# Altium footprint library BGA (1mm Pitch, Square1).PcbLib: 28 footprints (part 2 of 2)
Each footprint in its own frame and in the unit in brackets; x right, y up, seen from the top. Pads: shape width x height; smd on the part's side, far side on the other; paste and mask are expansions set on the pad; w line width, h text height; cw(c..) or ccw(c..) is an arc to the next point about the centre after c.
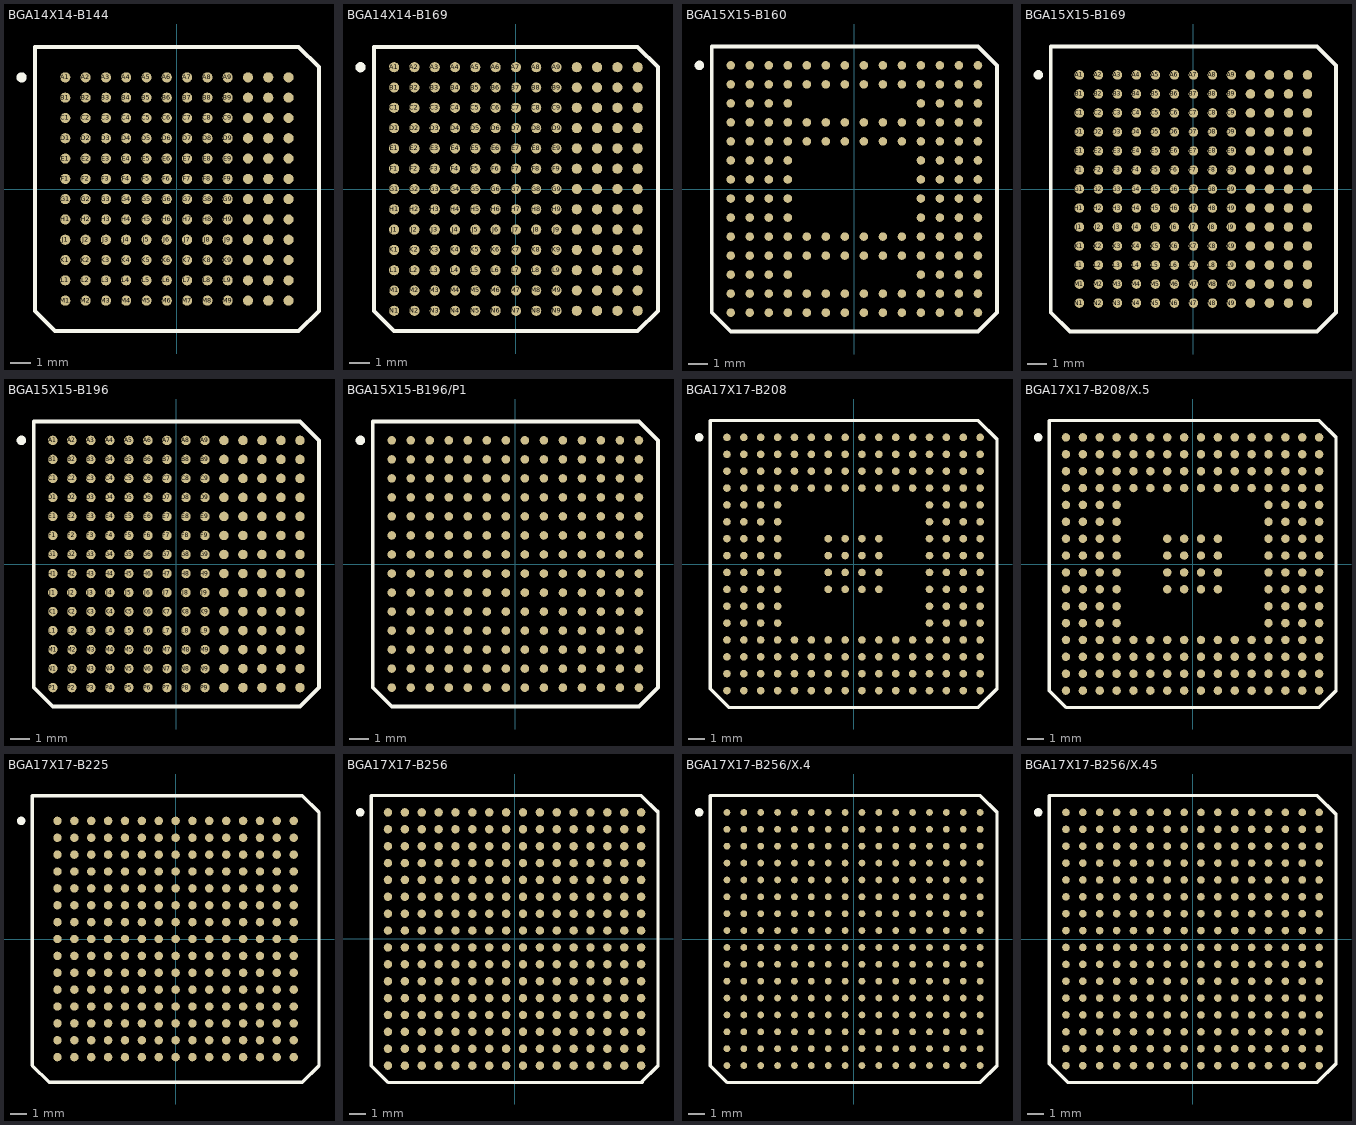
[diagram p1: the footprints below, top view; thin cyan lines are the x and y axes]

## BGA14X14-B144 [mm]
pads (144):
  round 0.5 smd: A1(-5.5,5.5) A2(-4.5,5.5) A3(-3.5,5.5) A4(-2.5,5.5) A5(-1.5,5.5) A6(-0.5,5.5) A7(0.5,5.5) A8(1.5,5.5) A9(2.5,5.5) A10(3.5,5.5) A11(4.5,5.5) A12(5.5,5.5) B1(-5.5,4.5) B2(-4.5,4.5) B3(-3.5,4.5) B4(-2.5,4.5) B5(-1.5,4.5) B6(-0.5,4.5) B7(0.5,4.5) B8(1.5,4.5) B9(2.5,4.5) B10(3.5,4.5) B11(4.5,4.5) B12(5.5,4.5) C1(-5.5,3.5) C2(-4.5,3.5) C3(-3.5,3.5) C4(-2.5,3.5) C5(-1.5,3.5) C6(-0.5,3.5) C7(0.5,3.5) C8(1.5,3.5) C9(2.5,3.5) C10(3.5,3.5) C11(4.5,3.5) C12(5.5,3.5) D1(-5.5,2.5) D2(-4.5,2.5) D3(-3.5,2.5) D4(-2.5,2.5) D5(-1.5,2.5) D6(-0.5,2.5) D7(0.5,2.5) D8(1.5,2.5) D9(2.5,2.5) D10(3.5,2.5) D11(4.5,2.5) D12(5.5,2.5) E1(-5.5,1.5) E2(-4.5,1.5) E3(-3.5,1.5) E4(-2.5,1.5) E5(-1.5,1.5) E6(-0.5,1.5) E7(0.5,1.5) E8(1.5,1.5) E9(2.5,1.5) E10(3.5,1.5) E11(4.5,1.5) E12(5.5,1.5) F1(-5.5,0.5) F2(-4.5,0.5) F3(-3.5,0.5) F4(-2.5,0.5) F5(-1.5,0.5) F6(-0.5,0.5) F7(0.5,0.5) F8(1.5,0.5) F9(2.5,0.5) F10(3.5,0.5) F11(4.5,0.5) F12(5.5,0.5) G1(-5.5,-0.5) G2(-4.5,-0.5) G3(-3.5,-0.5) G4(-2.5,-0.5) G5(-1.5,-0.5) G6(-0.5,-0.5) G7(0.5,-0.5) G8(1.5,-0.5) G9(2.5,-0.5) G10(3.5,-0.5) G11(4.5,-0.5) G12(5.5,-0.5) H1(-5.5,-1.5) H2(-4.5,-1.5) H3(-3.5,-1.5) H4(-2.5,-1.5) H5(-1.5,-1.5) H6(-0.5,-1.5) H7(0.5,-1.5) H8(1.5,-1.5) H9(2.5,-1.5) H10(3.5,-1.5) H11(4.5,-1.5) H12(5.5,-1.5) J1(-5.5,-2.5) J2(-4.5,-2.5) J3(-3.5,-2.5) J4(-2.5,-2.5) J5(-1.5,-2.5) J6(-0.5,-2.5) J7(0.5,-2.5) J8(1.5,-2.5) J9(2.5,-2.5) J10(3.5,-2.5) J11(4.5,-2.5) J12(5.5,-2.5) K1(-5.5,-3.5) K2(-4.5,-3.5) K3(-3.5,-3.5) K4(-2.5,-3.5) K5(-1.5,-3.5) K6(-0.5,-3.5) K7(0.5,-3.5) K8(1.5,-3.5) K9(2.5,-3.5) K10(3.5,-3.5) K11(4.5,-3.5) K12(5.5,-3.5) L1(-5.5,-4.5) L2(-4.5,-4.5) L3(-3.5,-4.5) L4(-2.5,-4.5) L5(-1.5,-4.5) L6(-0.5,-4.5) L7(0.5,-4.5) L8(1.5,-4.5) L9(2.5,-4.5) L10(3.5,-4.5) L11(4.5,-4.5) L12(5.5,-4.5) M1(-5.5,-5.5) M2(-4.5,-5.5) M3(-3.5,-5.5) M4(-2.5,-5.5) M5(-1.5,-5.5) M6(-0.5,-5.5) M7(0.5,-5.5) M8(1.5,-5.5) M9(2.5,-5.5) M10(3.5,-5.5) M11(4.5,-5.5) M12(5.5,-5.5)
Top Overlay:
  circle w0.25: c-7.655,5.5 r0.125
  lines w0.2: -7,-6 -6,-7 6,-7 7,-6 7,6 6,7 -7,7 -7,-6

## BGA14X14-B169 [mm]
pads (169):
  round 0.5 smd: A1(-6,6) A2(-5,6) A3(-4,6) A4(-3,6) A5(-2,6) A6(-1,6) A7(0,6) A8(1,6) A9(2,6) A10(3,6) A11(4,6) A12(5,6) A13(6,6) B1(-6,5) B2(-5,5) B3(-4,5) B4(-3,5) B5(-2,5) B6(-1,5) B7(0,5) B8(1,5) B9(2,5) B10(3,5) B11(4,5) B12(5,5) B13(6,5) C1(-6,4) C2(-5,4) C3(-4,4) C4(-3,4) C5(-2,4) C6(-1,4) C7(0,4) C8(1,4) C9(2,4) C10(3,4) C11(4,4) C12(5,4) C13(6,4) D1(-6,3) D2(-5,3) D3(-4,3) D4(-3,3) D5(-2,3) D6(-1,3) D7(0,3) D8(1,3) D9(2,3) D10(3,3) D11(4,3) D12(5,3) D13(6,3) E1(-6,2) E2(-5,2) E3(-4,2) E4(-3,2) E5(-2,2) E6(-1,2) E7(0,2) E8(1,2) E9(2,2) E10(3,2) E11(4,2) E12(5,2) E13(6,2) F1(-6,1) F2(-5,1) F3(-4,1) F4(-3,1) F5(-2,1) F6(-1,1) F7(0,1) F8(1,1) F9(2,1) F10(3,1) F11(4,1) F12(5,1) F13(6,1) G1(-6,0) G2(-5,0) G3(-4,0) G4(-3,0) G5(-2,0) G6(-1,0) G7(0,0) G8(1,0) G9(2,0) G10(3,0) G11(4,0) G12(5,0) G13(6,0) H1(-6,-1) H2(-5,-1) H3(-4,-1) H4(-3,-1) H5(-2,-1) H6(-1,-1) H7(0,-1) H8(1,-1) H9(2,-1) H10(3,-1) H11(4,-1) H12(5,-1) H13(6,-1) J1(-6,-2) J2(-5,-2) J3(-4,-2) J4(-3,-2) J5(-2,-2) J6(-1,-2) J7(0,-2) J8(1,-2) J9(2,-2) J10(3,-2) J11(4,-2) J12(5,-2) J13(6,-2) K1(-6,-3) K2(-5,-3) K3(-4,-3) K4(-3,-3) K5(-2,-3) K6(-1,-3) K7(0,-3) K8(1,-3) K9(2,-3) K10(3,-3) K11(4,-3) K12(5,-3) K13(6,-3) L1(-6,-4) L2(-5,-4) L3(-4,-4) L4(-3,-4) L5(-2,-4) L6(-1,-4) L7(0,-4) L8(1,-4) L9(2,-4) L10(3,-4) L11(4,-4) L12(5,-4) L13(6,-4) M1(-6,-5) M2(-5,-5) M3(-4,-5) M4(-3,-5) M5(-2,-5) M6(-1,-5) M7(0,-5) M8(1,-5) M9(2,-5) M10(3,-5) M11(4,-5) M12(5,-5) M13(6,-5) N1(-6,-6) N2(-5,-6) N3(-4,-6) N4(-3,-6) N5(-2,-6) N6(-1,-6) N7(0,-6) N8(1,-6) N9(2,-6) N10(3,-6) N11(4,-6) N12(5,-6) N13(6,-6)
Top Overlay:
  circle w0.25: c-7.655,6 r0.125
  lines w0.2: -7,-6 -7,7 6,7 7,6 7,-6 6,-7 -6,-7 -7,-6

## BGA15X15-B160 [mm]
pads (160):
  round 0.45 smd: A1(-6.5,6.5) A2(-5.5,6.5) A3(-4.5,6.5) A4(-3.5,6.5) A5(-2.5,6.5) A6(-1.5,6.5) A7(-0.5,6.5) A8(0.5,6.5) A9(1.5,6.5) A10(2.5,6.5) A11(3.5,6.5) A12(4.5,6.5) A13(5.5,6.5) A14(6.5,6.5) B1(-6.5,5.5) B2(-5.5,5.5) B3(-4.5,5.5) B4(-3.5,5.5) B5(-2.5,5.5) B6(-1.5,5.5) B7(-0.5,5.5) B8(0.5,5.5) B9(1.5,5.5) B10(2.5,5.5) B11(3.5,5.5) B12(4.5,5.5) B13(5.5,5.5) B14(6.5,5.5) C1(-6.5,4.5) C2(-5.5,4.5) C3(-4.5,4.5) C4(-3.5,4.5) C11(3.5,4.5) C12(4.5,4.5) C13(5.5,4.5) C14(6.5,4.5) D1(-6.5,3.5) D2(-5.5,3.5) D3(-4.5,3.5) D4(-3.5,3.5) D5(-2.5,3.5) D6(-1.5,3.5) D7(-0.5,3.5) D8(0.5,3.5) D9(1.5,3.5) D10(2.5,3.5) D11(3.5,3.5) D12(4.5,3.5) D13(5.5,3.5) D14(6.5,3.5) E1(-6.5,2.5) E2(-5.5,2.5) E3(-4.5,2.5) E4(-3.5,2.5) E5(-2.5,2.5) E6(-1.5,2.5) E7(-0.5,2.5) E8(0.5,2.5) E9(1.5,2.5) E10(2.5,2.5) E11(3.5,2.5) E12(4.5,2.5) E13(5.5,2.5) E14(6.5,2.5) F1(-6.5,1.5) F2(-5.5,1.5) F3(-4.5,1.5) F4(-3.5,1.5) F11(3.5,1.5) F12(4.5,1.5) F13(5.5,1.5) F14(6.5,1.5) G1(-6.5,0.5) G2(-5.5,0.5) G3(-4.5,0.5) G4(-3.5,0.5) G11(3.5,0.5) G12(4.5,0.5) G13(5.5,0.5) G14(6.5,0.5) H1(-6.5,-0.5) H2(-5.5,-0.5) H3(-4.5,-0.5) H4(-3.5,-0.5) H11(3.5,-0.5) H12(4.5,-0.5) H13(5.5,-0.5) H14(6.5,-0.5) J1(-6.5,-1.5) J2(-5.5,-1.5) J3(-4.5,-1.5) J4(-3.5,-1.5) J11(3.5,-1.5) J12(4.5,-1.5) J13(5.5,-1.5) J14(6.5,-1.5) K1(-6.5,-2.5) K2(-5.5,-2.5) K3(-4.5,-2.5) K4(-3.5,-2.5) K5(-2.5,-2.5) K6(-1.5,-2.5) K7(-0.5,-2.5) K8(0.5,-2.5) K9(1.5,-2.5) K10(2.5,-2.5) K11(3.5,-2.5) K12(4.5,-2.5) K13(5.5,-2.5) K14(6.5,-2.5) L1(-6.5,-3.5) L2(-5.5,-3.5) L3(-4.5,-3.5) L4(-3.5,-3.5) L5(-2.5,-3.5) L6(-1.5,-3.5) L7(-0.5,-3.5) L8(0.5,-3.5) L9(1.5,-3.5) L10(2.5,-3.5) L11(3.5,-3.5) L12(4.5,-3.5) L13(5.5,-3.5) L14(6.5,-3.5) M1(-6.5,-4.5) M2(-5.5,-4.5) M3(-4.5,-4.5) M4(-3.5,-4.5) M11(3.5,-4.5) M12(4.5,-4.5) M13(5.5,-4.5) M14(6.5,-4.5) N1(-6.5,-5.5) N2(-5.5,-5.5) N3(-4.5,-5.5) N4(-3.5,-5.5) N5(-2.5,-5.5) N6(-1.5,-5.5) N7(-0.5,-5.5) N8(0.5,-5.5) N9(1.5,-5.5) N10(2.5,-5.5) N11(3.5,-5.5) N12(4.5,-5.5) N13(5.5,-5.5) N14(6.5,-5.5) P1(-6.5,-6.5) P2(-5.5,-6.5) P3(-4.5,-6.5) P4(-3.5,-6.5) P5(-2.5,-6.5) P6(-1.5,-6.5) P7(-0.5,-6.5) P8(0.5,-6.5) P9(1.5,-6.5) P10(2.5,-6.5) P11(3.5,-6.5) P12(4.5,-6.5) P13(5.5,-6.5) P14(6.5,-6.5)
Top Overlay:
  circle w0.25: c-8.15,6.5 r0.125
  lines w0.2: -7.5,-6.5 -7.5,7.5 6.5,7.5 7.5,6.5 7.5,-6.5 6.5,-7.5 -6.5,-7.5 -7.5,-6.5

## BGA15X15-B169 [mm]
pads (169):
  round 0.5 smd: A1(-6,6) A2(-5,6) A3(-4,6) A4(-3,6) A5(-2,6) A6(-1,6) A7(0,6) A8(1,6) A9(2,6) A10(3,6) A11(4,6) A12(5,6) A13(6,6) B1(-6,5) B2(-5,5) B3(-4,5) B4(-3,5) B5(-2,5) B6(-1,5) B7(0,5) B8(1,5) B9(2,5) B10(3,5) B11(4,5) B12(5,5) B13(6,5) C1(-6,4) C2(-5,4) C3(-4,4) C4(-3,4) C5(-2,4) C6(-1,4) C7(0,4) C8(1,4) C9(2,4) C10(3,4) C11(4,4) C12(5,4) C13(6,4) D1(-6,3) D2(-5,3) D3(-4,3) D4(-3,3) D5(-2,3) D6(-1,3) D7(0,3) D8(1,3) D9(2,3) D10(3,3) D11(4,3) D12(5,3) D13(6,3) E1(-6,2) E2(-5,2) E3(-4,2) E4(-3,2) E5(-2,2) E6(-1,2) E7(0,2) E8(1,2) E9(2,2) E10(3,2) E11(4,2) E12(5,2) E13(6,2) F1(-6,1) F2(-5,1) F3(-4,1) F4(-3,1) F5(-2,1) F6(-1,1) F7(0,1) F8(1,1) F9(2,1) F10(3,1) F11(4,1) F12(5,1) F13(6,1) G1(-6,0) G2(-5,0) G3(-4,0) G4(-3,0) G5(-2,0) G6(-1,0) G7(0,0) G8(1,0) G9(2,0) G10(3,0) G11(4,0) G12(5,0) G13(6,0) H1(-6,-1) H2(-5,-1) H3(-4,-1) H4(-3,-1) H5(-2,-1) H6(-1,-1) H7(0,-1) H8(1,-1) H9(2,-1) H10(3,-1) H11(4,-1) H12(5,-1) H13(6,-1) J1(-6,-2) J2(-5,-2) J3(-4,-2) J4(-3,-2) J5(-2,-2) J6(-1,-2) J7(0,-2) J8(1,-2) J9(2,-2) J10(3,-2) J11(4,-2) J12(5,-2) J13(6,-2) K1(-6,-3) K2(-5,-3) K3(-4,-3) K4(-3,-3) K5(-2,-3) K6(-1,-3) K7(0,-3) K8(1,-3) K9(2,-3) K10(3,-3) K11(4,-3) K12(5,-3) K13(6,-3) L1(-6,-4) L2(-5,-4) L3(-4,-4) L4(-3,-4) L5(-2,-4) L6(-1,-4) L7(0,-4) L8(1,-4) L9(2,-4) L10(3,-4) L11(4,-4) L12(5,-4) L13(6,-4) M1(-6,-5) M2(-5,-5) M3(-4,-5) M4(-3,-5) M5(-2,-5) M6(-1,-5) M7(0,-5) M8(1,-5) M9(2,-5) M10(3,-5) M11(4,-5) M12(5,-5) M13(6,-5) N1(-6,-6) N2(-5,-6) N3(-4,-6) N4(-3,-6) N5(-2,-6) N6(-1,-6) N7(0,-6) N8(1,-6) N9(2,-6) N10(3,-6) N11(4,-6) N12(5,-6) N13(6,-6)
Top Overlay:
  circle w0.25: c-8.155,6 r0.125
  lines w0.2: -7.5,-6.5 -7.5,7.5 6.5,7.5 7.5,6.5 7.5,-6.5 6.5,-7.5 -6.5,-7.5 -7.5,-6.5

## BGA15X15-B196 [mm]
pads (196):
  round 0.5 smd: A1(-6.5,6.5) A2(-5.5,6.5) A3(-4.5,6.5) A4(-3.5,6.5) A5(-2.5,6.5) A6(-1.5,6.5) A7(-0.5,6.5) A8(0.5,6.5) A9(1.5,6.5) A10(2.5,6.5) A11(3.5,6.5) A12(4.5,6.5) A13(5.5,6.5) A14(6.5,6.5) B1(-6.5,5.5) B2(-5.5,5.5) B3(-4.5,5.5) B4(-3.5,5.5) B5(-2.5,5.5) B6(-1.5,5.5) B7(-0.5,5.5) B8(0.5,5.5) B9(1.5,5.5) B10(2.5,5.5) B11(3.5,5.5) B12(4.5,5.5) B13(5.5,5.5) B14(6.5,5.5) C1(-6.5,4.5) C2(-5.5,4.5) C3(-4.5,4.5) C4(-3.5,4.5) C5(-2.5,4.5) C6(-1.5,4.5) C7(-0.5,4.5) C8(0.5,4.5) C9(1.5,4.5) C10(2.5,4.5) C11(3.5,4.5) C12(4.5,4.5) C13(5.5,4.5) C14(6.5,4.5) D1(-6.5,3.5) D2(-5.5,3.5) D3(-4.5,3.5) D4(-3.5,3.5) D5(-2.5,3.5) D6(-1.5,3.5) D7(-0.5,3.5) D8(0.5,3.5) D9(1.5,3.5) D10(2.5,3.5) D11(3.5,3.5) D12(4.5,3.5) D13(5.5,3.5) D14(6.5,3.5) E1(-6.5,2.5) E2(-5.5,2.5) E3(-4.5,2.5) E4(-3.5,2.5) E5(-2.5,2.5) E6(-1.5,2.5) E7(-0.5,2.5) E8(0.5,2.5) E9(1.5,2.5) E10(2.5,2.5) E11(3.5,2.5) E12(4.5,2.5) E13(5.5,2.5) E14(6.5,2.5) F1(-6.5,1.5) F2(-5.5,1.5) F3(-4.5,1.5) F4(-3.5,1.5) F5(-2.5,1.5) F6(-1.5,1.5) F7(-0.5,1.5) F8(0.5,1.5) F9(1.5,1.5) F10(2.5,1.5) F11(3.5,1.5) F12(4.5,1.5) F13(5.5,1.5) F14(6.5,1.5) G1(-6.5,0.5) G2(-5.5,0.5) G3(-4.5,0.5) G4(-3.5,0.5) G5(-2.5,0.5) G6(-1.5,0.5) G7(-0.5,0.5) G8(0.5,0.5) G9(1.5,0.5) G10(2.5,0.5) G11(3.5,0.5) G12(4.5,0.5) G13(5.5,0.5) G14(6.5,0.5) H1(-6.5,-0.5) H2(-5.5,-0.5) H3(-4.5,-0.5) H4(-3.5,-0.5) H5(-2.5,-0.5) H6(-1.5,-0.5) H7(-0.5,-0.5) H8(0.5,-0.5) H9(1.5,-0.5) H10(2.5,-0.5) H11(3.5,-0.5) H12(4.5,-0.5) H13(5.5,-0.5) H14(6.5,-0.5) J1(-6.5,-1.5) J2(-5.5,-1.5) J3(-4.5,-1.5) J4(-3.5,-1.5) J5(-2.5,-1.5) J6(-1.5,-1.5) J7(-0.5,-1.5) J8(0.5,-1.5) J9(1.5,-1.5) J10(2.5,-1.5) J11(3.5,-1.5) J12(4.5,-1.5) J13(5.5,-1.5) J14(6.5,-1.5) K1(-6.5,-2.5) K2(-5.5,-2.5) K3(-4.5,-2.5) K4(-3.5,-2.5) K5(-2.5,-2.5) K6(-1.5,-2.5) K7(-0.5,-2.5) K8(0.5,-2.5) K9(1.5,-2.5) K10(2.5,-2.5) K11(3.5,-2.5) K12(4.5,-2.5) K13(5.5,-2.5) K14(6.5,-2.5) L1(-6.5,-3.5) L2(-5.5,-3.5) L3(-4.5,-3.5) L4(-3.5,-3.5) L5(-2.5,-3.5) L6(-1.5,-3.5) L7(-0.5,-3.5) L8(0.5,-3.5) L9(1.5,-3.5) L10(2.5,-3.5) L11(3.5,-3.5) L12(4.5,-3.5) L13(5.5,-3.5) L14(6.5,-3.5) M1(-6.5,-4.5) M2(-5.5,-4.5) M3(-4.5,-4.5) M4(-3.5,-4.5) M5(-2.5,-4.5) M6(-1.5,-4.5) M7(-0.5,-4.5) M8(0.5,-4.5) M9(1.5,-4.5) M10(2.5,-4.5) M11(3.5,-4.5) M12(4.5,-4.5) M13(5.5,-4.5) M14(6.5,-4.5) N1(-6.5,-5.5) N2(-5.5,-5.5) N3(-4.5,-5.5) N4(-3.5,-5.5) N5(-2.5,-5.5) N6(-1.5,-5.5) N7(-0.5,-5.5) N8(0.5,-5.5) N9(1.5,-5.5) N10(2.5,-5.5) N11(3.5,-5.5) N12(4.5,-5.5) N13(5.5,-5.5) N14(6.5,-5.5) P1(-6.5,-6.5) P2(-5.5,-6.5) P3(-4.5,-6.5) P4(-3.5,-6.5) P5(-2.5,-6.5) P6(-1.5,-6.5) P7(-0.5,-6.5) P8(0.5,-6.5) P9(1.5,-6.5) P10(2.5,-6.5) P11(3.5,-6.5) P12(4.5,-6.5) P13(5.5,-6.5) P14(6.5,-6.5)
Top Overlay:
  circle w0.25: c-8.15,6.5 r0.125
  lines w0.2: -7.5,-6.5 -6.5,-7.5 6.5,-7.5 7.5,-6.5 7.5,6.5 6.5,7.5 -7.5,7.5 -7.5,-6.5

## BGA15X15-B196/P1 [mm]
pads (196):
  round 0.45 smd: A1(-6.5,6.5) A2(-5.5,6.5) A3(-4.5,6.5) A4(-3.5,6.5) A5(-2.5,6.5) A6(-1.5,6.5) A7(-0.5,6.5) A8(0.5,6.5) A9(1.5,6.5) A10(2.5,6.5) A11(3.5,6.5) A12(4.5,6.5) A13(5.5,6.5) A14(6.5,6.5) B1(-6.5,5.5) B2(-5.5,5.5) B3(-4.5,5.5) B4(-3.5,5.5) B5(-2.5,5.5) B6(-1.5,5.5) B7(-0.5,5.5) B8(0.5,5.5) B9(1.5,5.5) B10(2.5,5.5) B11(3.5,5.5) B12(4.5,5.5) B13(5.5,5.5) B14(6.5,5.5) C1(-6.5,4.5) C2(-5.5,4.5) C3(-4.5,4.5) C4(-3.5,4.5) C5(-2.5,4.5) C6(-1.5,4.5) C7(-0.5,4.5) C8(0.5,4.5) C9(1.5,4.5) C10(2.5,4.5) C11(3.5,4.5) C12(4.5,4.5) C13(5.5,4.5) C14(6.5,4.5) D1(-6.5,3.5) D2(-5.5,3.5) D3(-4.5,3.5) D4(-3.5,3.5) D5(-2.5,3.5) D6(-1.5,3.5) D7(-0.5,3.5) D8(0.5,3.5) D9(1.5,3.5) D10(2.5,3.5) D11(3.5,3.5) D12(4.5,3.5) D13(5.5,3.5) D14(6.5,3.5) E1(-6.5,2.5) E2(-5.5,2.5) E3(-4.5,2.5) E4(-3.5,2.5) E5(-2.5,2.5) E6(-1.5,2.5) E7(-0.5,2.5) E8(0.5,2.5) E9(1.5,2.5) E10(2.5,2.5) E11(3.5,2.5) E12(4.5,2.5) E13(5.5,2.5) E14(6.5,2.5) F1(-6.5,1.5) F2(-5.5,1.5) F3(-4.5,1.5) F4(-3.5,1.5) F5(-2.5,1.5) F6(-1.5,1.5) F7(-0.5,1.5) F8(0.5,1.5) F9(1.5,1.5) F10(2.5,1.5) F11(3.5,1.5) F12(4.5,1.5) F13(5.5,1.5) F14(6.5,1.5) G1(-6.5,0.5) G2(-5.5,0.5) G3(-4.5,0.5) G4(-3.5,0.5) G5(-2.5,0.5) G6(-1.5,0.5) G7(-0.5,0.5) G8(0.5,0.5) G9(1.5,0.5) G10(2.5,0.5) G11(3.5,0.5) G12(4.5,0.5) G13(5.5,0.5) G14(6.5,0.5) H1(-6.5,-0.5) H2(-5.5,-0.5) H3(-4.5,-0.5) H4(-3.5,-0.5) H5(-2.5,-0.5) H6(-1.5,-0.5) H7(-0.5,-0.5) H8(0.5,-0.5) H9(1.5,-0.5) H10(2.5,-0.5) H11(3.5,-0.5) H12(4.5,-0.5) H13(5.5,-0.5) H14(6.5,-0.5) J1(-6.5,-1.5) J2(-5.5,-1.5) J3(-4.5,-1.5) J4(-3.5,-1.5) J5(-2.5,-1.5) J6(-1.5,-1.5) J7(-0.5,-1.5) J8(0.5,-1.5) J9(1.5,-1.5) J10(2.5,-1.5) J11(3.5,-1.5) J12(4.5,-1.5) J13(5.5,-1.5) J14(6.5,-1.5) K1(-6.5,-2.5) K2(-5.5,-2.5) K3(-4.5,-2.5) K4(-3.5,-2.5) K5(-2.5,-2.5) K6(-1.5,-2.5) K7(-0.5,-2.5) K8(0.5,-2.5) K9(1.5,-2.5) K10(2.5,-2.5) K11(3.5,-2.5) K12(4.5,-2.5) K13(5.5,-2.5) K14(6.5,-2.5) L1(-6.5,-3.5) L2(-5.5,-3.5) L3(-4.5,-3.5) L4(-3.5,-3.5) L5(-2.5,-3.5) L6(-1.5,-3.5) L7(-0.5,-3.5) L8(0.5,-3.5) L9(1.5,-3.5) L10(2.5,-3.5) L11(3.5,-3.5) L12(4.5,-3.5) L13(5.5,-3.5) L14(6.5,-3.5) M1(-6.5,-4.5) M2(-5.5,-4.5) M3(-4.5,-4.5) M4(-3.5,-4.5) M5(-2.5,-4.5) M6(-1.5,-4.5) M7(-0.5,-4.5) M8(0.5,-4.5) M9(1.5,-4.5) M10(2.5,-4.5) M11(3.5,-4.5) M12(4.5,-4.5) M13(5.5,-4.5) M14(6.5,-4.5) N1(-6.5,-5.5) N2(-5.5,-5.5) N3(-4.5,-5.5) N4(-3.5,-5.5) N5(-2.5,-5.5) N6(-1.5,-5.5) N7(-0.5,-5.5) N8(0.5,-5.5) N9(1.5,-5.5) N10(2.5,-5.5) N11(3.5,-5.5) N12(4.5,-5.5) N13(5.5,-5.5) N14(6.5,-5.5) P1(-6.5,-6.5) P2(-5.5,-6.5) P3(-4.5,-6.5) P4(-3.5,-6.5) P5(-2.5,-6.5) P6(-1.5,-6.5) P7(-0.5,-6.5) P8(0.5,-6.5) P9(1.5,-6.5) P10(2.5,-6.5) P11(3.5,-6.5) P12(4.5,-6.5) P13(5.5,-6.5) P14(6.5,-6.5)
Top Overlay:
  circle w0.25: c-8.15,6.5 r0.125
  lines w0.2: -7.5,-6.5 -7.5,7.5 6.5,7.5 7.5,6.5 7.5,-6.5 6.5,-7.5 -6.5,-7.5 -7.5,-6.5

## BGA17X17-B208 [mm]
pads (208):
  round 0.45 smd: A1(-7.5,7.5) A2(-6.5,7.5) A3(-5.5,7.5) A4(-4.5,7.5) A5(-3.5,7.5) A6(-2.5,7.5) A7(-1.5,7.5) A8(-0.5,7.5) A9(0.5,7.5) A10(1.5,7.5) A11(2.5,7.5) A12(3.5,7.5) A13(4.5,7.5) A14(5.5,7.5) A15(6.5,7.5) A16(7.5,7.5) B1(-7.5,6.5) B2(-6.5,6.5) B3(-5.5,6.5) B4(-4.5,6.5) B5(-3.5,6.5) B6(-2.5,6.5) B7(-1.5,6.5) B8(-0.5,6.5) B9(0.5,6.5) B10(1.5,6.5) B11(2.5,6.5) B12(3.5,6.5) B13(4.5,6.5) B14(5.5,6.5) B15(6.5,6.5) B16(7.5,6.5) C1(-7.5,5.5) C2(-6.5,5.5) C3(-5.5,5.5) C4(-4.5,5.5) C5(-3.5,5.5) C6(-2.5,5.5) C7(-1.5,5.5) C8(-0.5,5.5) C9(0.5,5.5) C10(1.5,5.5) C11(2.5,5.5) C12(3.5,5.5) C13(4.5,5.5) C14(5.5,5.5) C15(6.5,5.5) C16(7.5,5.5) D1(-7.5,4.5) D2(-6.5,4.5) D3(-5.5,4.5) D4(-4.5,4.5) D5(-3.5,4.5) D6(-2.5,4.5) D7(-1.5,4.5) D8(-0.5,4.5) D9(0.5,4.5) D10(1.5,4.5) D11(2.5,4.5) D12(3.5,4.5) D13(4.5,4.5) D14(5.5,4.5) D15(6.5,4.5) D16(7.5,4.5) E1(-7.5,3.5) E2(-6.5,3.5) E3(-5.5,3.5) E4(-4.5,3.5) E13(4.5,3.5) E14(5.5,3.5) E15(6.5,3.5) E16(7.5,3.5) F1(-7.5,2.5) F2(-6.5,2.5) F3(-5.5,2.5) F4(-4.5,2.5) F13(4.5,2.5) F14(5.5,2.5) F15(6.5,2.5) F16(7.5,2.5) G1(-7.5,1.5) G2(-6.5,1.5) G3(-5.5,1.5) G4(-4.5,1.5) G7(-1.5,1.5) G8(-0.5,1.5) G9(0.5,1.5) G10(1.5,1.5) G13(4.5,1.5) G14(5.5,1.5) G15(6.5,1.5) G16(7.5,1.5) H1(-7.5,0.5) H2(-6.5,0.5) H3(-5.5,0.5) H4(-4.5,0.5) H7(-1.5,0.5) H8(-0.5,0.5) H9(0.5,0.5) H10(1.5,0.5) H13(4.5,0.5) H14(5.5,0.5) H15(6.5,0.5) H16(7.5,0.5) J1(-7.5,-0.5) J2(-6.5,-0.5) J3(-5.5,-0.5) J4(-4.5,-0.5) J7(-1.5,-0.5) J8(-0.5,-0.5) J9(0.5,-0.5) J10(1.5,-0.5) J13(4.5,-0.5) J14(5.5,-0.5) J15(6.5,-0.5) J16(7.5,-0.5) K1(-7.5,-1.5) K2(-6.5,-1.5) K3(-5.5,-1.5) K4(-4.5,-1.5) K7(-1.5,-1.5) K8(-0.5,-1.5) K9(0.5,-1.5) K10(1.5,-1.5) K13(4.5,-1.5) K14(5.5,-1.5) K15(6.5,-1.5) K16(7.5,-1.5) L1(-7.5,-2.5) L2(-6.5,-2.5) L3(-5.5,-2.5) L4(-4.5,-2.5) L13(4.5,-2.5) L14(5.5,-2.5) L15(6.5,-2.5) L16(7.5,-2.5) M1(-7.5,-3.5) M2(-6.5,-3.5) M3(-5.5,-3.5) M4(-4.5,-3.5) M13(4.5,-3.5) M14(5.5,-3.5) M15(6.5,-3.5) M16(7.5,-3.5) N1(-7.5,-4.5) N2(-6.5,-4.5) N3(-5.5,-4.5) N4(-4.5,-4.5) N5(-3.5,-4.5) N6(-2.5,-4.5) N7(-1.5,-4.5) N8(-0.5,-4.5) N9(0.5,-4.5) N10(1.5,-4.5) N11(2.5,-4.5) N12(3.5,-4.5) N13(4.5,-4.5) N14(5.5,-4.5) N15(6.5,-4.5) N16(7.5,-4.5) P1(-7.5,-5.5) P2(-6.5,-5.5) P3(-5.5,-5.5) P4(-4.5,-5.5) P5(-3.5,-5.5) P6(-2.5,-5.5) P7(-1.5,-5.5) P8(-0.5,-5.5) P9(0.5,-5.5) P10(1.5,-5.5) P11(2.5,-5.5) P12(3.5,-5.5) P13(4.5,-5.5) P14(5.5,-5.5) P15(6.5,-5.5) P16(7.5,-5.5) R1(-7.5,-6.5) R2(-6.5,-6.5) R3(-5.5,-6.5) R4(-4.5,-6.5) R5(-3.5,-6.5) R6(-2.5,-6.5) R7(-1.5,-6.5) R8(-0.5,-6.5) R9(0.5,-6.5) R10(1.5,-6.5) R11(2.5,-6.5) R12(3.5,-6.5) R13(4.5,-6.5) R14(5.5,-6.5) R15(6.5,-6.5) R16(7.5,-6.5) T1(-7.5,-7.5) T2(-6.5,-7.5) T3(-5.5,-7.5) T4(-4.5,-7.5) T5(-3.5,-7.5) T6(-2.5,-7.5) T7(-1.5,-7.5) T8(-0.5,-7.5) T9(0.5,-7.5) T10(1.5,-7.5) T11(2.5,-7.5) T12(3.5,-7.5) T13(4.5,-7.5) T14(5.5,-7.5) T15(6.5,-7.5) T16(7.5,-7.5)
Top Overlay:
  circle w0.25: c-9.15,7.5 r0.125
  lines w0.2: -8.5,-7.384 -8.5,8.5 7.384,8.5 8.5,7.384 8.5,-7.384 7.384,-8.5 -7.384,-8.5 -8.5,-7.384

## BGA17X17-B208/X.5 [mm]
pads (208):
  round 0.5 smd: A1(-7.5,7.5) A2(-6.5,7.5) A3(-5.5,7.5) A4(-4.5,7.5) A5(-3.5,7.5) A6(-2.5,7.5) A7(-1.5,7.5) A8(-0.5,7.5) A9(0.5,7.5) A10(1.5,7.5) A11(2.5,7.5) A12(3.5,7.5) A13(4.5,7.5) A14(5.5,7.5) A15(6.5,7.5) A16(7.5,7.5) B1(-7.5,6.5) B2(-6.5,6.5) B3(-5.5,6.5) B4(-4.5,6.5) B5(-3.5,6.5) B6(-2.5,6.5) B7(-1.5,6.5) B8(-0.5,6.5) B9(0.5,6.5) B10(1.5,6.5) B11(2.5,6.5) B12(3.5,6.5) B13(4.5,6.5) B14(5.5,6.5) B15(6.5,6.5) B16(7.5,6.5) C1(-7.5,5.5) C2(-6.5,5.5) C3(-5.5,5.5) C4(-4.5,5.5) C5(-3.5,5.5) C6(-2.5,5.5) C7(-1.5,5.5) C8(-0.5,5.5) C9(0.5,5.5) C10(1.5,5.5) C11(2.5,5.5) C12(3.5,5.5) C13(4.5,5.5) C14(5.5,5.5) C15(6.5,5.5) C16(7.5,5.5) D1(-7.5,4.5) D2(-6.5,4.5) D3(-5.5,4.5) D4(-4.5,4.5) D5(-3.5,4.5) D6(-2.5,4.5) D7(-1.5,4.5) D8(-0.5,4.5) D9(0.5,4.5) D10(1.5,4.5) D11(2.5,4.5) D12(3.5,4.5) D13(4.5,4.5) D14(5.5,4.5) D15(6.5,4.5) D16(7.5,4.5) E1(-7.5,3.5) E2(-6.5,3.5) E3(-5.5,3.5) E4(-4.5,3.5) E13(4.5,3.5) E14(5.5,3.5) E15(6.5,3.5) E16(7.5,3.5) F1(-7.5,2.5) F2(-6.5,2.5) F3(-5.5,2.5) F4(-4.5,2.5) F13(4.5,2.5) F14(5.5,2.5) F15(6.5,2.5) F16(7.5,2.5) G1(-7.5,1.5) G2(-6.5,1.5) G3(-5.5,1.5) G4(-4.5,1.5) G7(-1.5,1.5) G8(-0.5,1.5) G9(0.5,1.5) G10(1.5,1.5) G13(4.5,1.5) G14(5.5,1.5) G15(6.5,1.5) G16(7.5,1.5) H1(-7.5,0.5) H2(-6.5,0.5) H3(-5.5,0.5) H4(-4.5,0.5) H7(-1.5,0.5) H8(-0.5,0.5) H9(0.5,0.5) H10(1.5,0.5) H13(4.5,0.5) H14(5.5,0.5) H15(6.5,0.5) H16(7.5,0.5) J1(-7.5,-0.5) J2(-6.5,-0.5) J3(-5.5,-0.5) J4(-4.5,-0.5) J7(-1.5,-0.5) J8(-0.5,-0.5) J9(0.5,-0.5) J10(1.5,-0.5) J13(4.5,-0.5) J14(5.5,-0.5) J15(6.5,-0.5) J16(7.5,-0.5) K1(-7.5,-1.5) K2(-6.5,-1.5) K3(-5.5,-1.5) K4(-4.5,-1.5) K7(-1.5,-1.5) K8(-0.5,-1.5) K9(0.5,-1.5) K10(1.5,-1.5) K13(4.5,-1.5) K14(5.5,-1.5) K15(6.5,-1.5) K16(7.5,-1.5) L1(-7.5,-2.5) L2(-6.5,-2.5) L3(-5.5,-2.5) L4(-4.5,-2.5) L13(4.5,-2.5) L14(5.5,-2.5) L15(6.5,-2.5) L16(7.5,-2.5) M1(-7.5,-3.5) M2(-6.5,-3.5) M3(-5.5,-3.5) M4(-4.5,-3.5) M13(4.5,-3.5) M14(5.5,-3.5) M15(6.5,-3.5) M16(7.5,-3.5) N1(-7.5,-4.5) N2(-6.5,-4.5) N3(-5.5,-4.5) N4(-4.5,-4.5) N5(-3.5,-4.5) N6(-2.5,-4.5) N7(-1.5,-4.5) N8(-0.5,-4.5) N9(0.5,-4.5) N10(1.5,-4.5) N11(2.5,-4.5) N12(3.5,-4.5) N13(4.5,-4.5) N14(5.5,-4.5) N15(6.5,-4.5) N16(7.5,-4.5) P1(-7.5,-5.5) P2(-6.5,-5.5) P3(-5.5,-5.5) P4(-4.5,-5.5) P5(-3.5,-5.5) P6(-2.5,-5.5) P7(-1.5,-5.5) P8(-0.5,-5.5) P9(0.5,-5.5) P10(1.5,-5.5) P11(2.5,-5.5) P12(3.5,-5.5) P13(4.5,-5.5) P14(5.5,-5.5) P15(6.5,-5.5) P16(7.5,-5.5) R1(-7.5,-6.5) R2(-6.5,-6.5) R3(-5.5,-6.5) R4(-4.5,-6.5) R5(-3.5,-6.5) R6(-2.5,-6.5) R7(-1.5,-6.5) R8(-0.5,-6.5) R9(0.5,-6.5) R10(1.5,-6.5) R11(2.5,-6.5) R12(3.5,-6.5) R13(4.5,-6.5) R14(5.5,-6.5) R15(6.5,-6.5) R16(7.5,-6.5) T1(-7.5,-7.5) T2(-6.5,-7.5) T3(-5.5,-7.5) T4(-4.5,-7.5) T5(-3.5,-7.5) T6(-2.5,-7.5) T7(-1.5,-7.5) T8(-0.5,-7.5) T9(0.5,-7.5) T10(1.5,-7.5) T11(2.5,-7.5) T12(3.5,-7.5) T13(4.5,-7.5) T14(5.5,-7.5) T15(6.5,-7.5) T16(7.5,-7.5)
Top Overlay:
  circle w0.25: c-9.15,7.5 r0.125
  lines w0.2: -8.5,-7.5 -7.5,-8.5 7.5,-8.5 8.5,-7.5 8.5,7.5 7.5,8.5 -8.5,8.5 -8.5,-7.5

## BGA17X17-B225 [mm]
pads (225):
  round 0.5 smd: A1(-7,7) A2(-6,7) A3(-5,7) A4(-4,7) A5(-3,7) A6(-2,7) A7(-1,7) A8(0,7) A9(1,7) A10(2,7) A11(3,7) A12(4,7) A13(5,7) A14(6,7) A15(7,7) B1(-7,6) B2(-6,6) B3(-5,6) B4(-4,6) B5(-3,6) B6(-2,6) B7(-1,6) B8(0,6) B9(1,6) B10(2,6) B11(3,6) B12(4,6) B13(5,6) B14(6,6) B15(7,6) C1(-7,5) C2(-6,5) C3(-5,5) C4(-4,5) C5(-3,5) C6(-2,5) C7(-1,5) C8(0,5) C9(1,5) C10(2,5) C11(3,5) C12(4,5) C13(5,5) C14(6,5) C15(7,5) D1(-7,4) D2(-6,4) D3(-5,4) D4(-4,4) D5(-3,4) D6(-2,4) D7(-1,4) D8(0,4) D9(1,4) D10(2,4) D11(3,4) D12(4,4) D13(5,4) D14(6,4) D15(7,4) E1(-7,3) E2(-6,3) E3(-5,3) E4(-4,3) E5(-3,3) E6(-2,3) E7(-1,3) E8(0,3) E9(1,3) E10(2,3) E11(3,3) E12(4,3) E13(5,3) E14(6,3) E15(7,3) F1(-7,2) F2(-6,2) F3(-5,2) F4(-4,2) F5(-3,2) F6(-2,2) F7(-1,2) F8(0,2) F9(1,2) F10(2,2) F11(3,2) F12(4,2) F13(5,2) F14(6,2) F15(7,2) G1(-7,1) G2(-6,1) G3(-5,1) G4(-4,1) G5(-3,1) G6(-2,1) G7(-1,1) G8(0,1) G9(1,1) G10(2,1) G11(3,1) G12(4,1) G13(5,1) G14(6,1) G15(7,1) H1(-7,0) H2(-6,0) H3(-5,0) H4(-4,0) H5(-3,0) H6(-2,0) H7(-1,0) H8(0,0) H9(1,0) H10(2,0) H11(3,0) H12(4,0) H13(5,0) H14(6,0) H15(7,0) J1(-7,-1) J2(-6,-1) J3(-5,-1) J4(-4,-1) J5(-3,-1) J6(-2,-1) J7(-1,-1) J8(0,-1) J9(1,-1) J10(2,-1) J11(3,-1) J12(4,-1) J13(5,-1) J14(6,-1) J15(7,-1) K1(-7,-2) K2(-6,-2) K3(-5,-2) K4(-4,-2) K5(-3,-2) K6(-2,-2) K7(-1,-2) K8(0,-2) K9(1,-2) K10(2,-2) K11(3,-2) K12(4,-2) K13(5,-2) K14(6,-2) K15(7,-2) L1(-7,-3) L2(-6,-3) L3(-5,-3) L4(-4,-3) L5(-3,-3) L6(-2,-3) L7(-1,-3) L8(0,-3) L9(1,-3) L10(2,-3) L11(3,-3) L12(4,-3) L13(5,-3) L14(6,-3) L15(7,-3) M1(-7,-4) M2(-6,-4) M3(-5,-4) M4(-4,-4) M5(-3,-4) M6(-2,-4) M7(-1,-4) M8(0,-4) M9(1,-4) M10(2,-4) M11(3,-4) M12(4,-4) M13(5,-4) M14(6,-4) M15(7,-4) N1(-7,-5) N2(-6,-5) N3(-5,-5) N4(-4,-5) N5(-3,-5) N6(-2,-5) N7(-1,-5) N8(0,-5) N9(1,-5) N10(2,-5) N11(3,-5) N12(4,-5) N13(5,-5) N14(6,-5) N15(7,-5) P1(-7,-6) P2(-6,-6) P3(-5,-6) P4(-4,-6) P5(-3,-6) P6(-2,-6) P7(-1,-6) P8(0,-6) P9(1,-6) P10(2,-6) P11(3,-6) P12(4,-6) P13(5,-6) P14(6,-6) P15(7,-6) R1(-7,-7) R2(-6,-7) R3(-5,-7) R4(-4,-7) R5(-3,-7) R6(-2,-7) R7(-1,-7) R8(0,-7) R9(1,-7) R10(2,-7) R11(3,-7) R12(4,-7) R13(5,-7) R14(6,-7) R15(7,-7)
Top Overlay:
  circle w0.25: c-9.155,7 r0.125
  lines w0.2: -8.5,-7.5 -7.5,-8.5 7.5,-8.5 8.5,-7.5 8.5,7.5 7.5,8.5 -8.5,8.5 -8.5,-7.5

## BGA17X17-B256 [mm]
pads (256):
  round 0.5 smd: A1(-7.5,7.5) A2(-6.5,7.5) A3(-5.5,7.5) A4(-4.5,7.5) A5(-3.5,7.5) A6(-2.5,7.5) A7(-1.5,7.5) A8(-0.5,7.5) A9(0.5,7.5) A10(1.5,7.5) A11(2.5,7.5) A12(3.5,7.5) A13(4.5,7.5) A14(5.5,7.5) A15(6.5,7.5) A16(7.5,7.5) B1(-7.5,6.5) B2(-6.5,6.5) B3(-5.5,6.5) B4(-4.5,6.5) B5(-3.5,6.5) B6(-2.5,6.5) B7(-1.5,6.5) B8(-0.5,6.5) B9(0.5,6.5) B10(1.5,6.5) B11(2.5,6.5) B12(3.5,6.5) B13(4.5,6.5) B14(5.5,6.5) B15(6.5,6.5) B16(7.5,6.5) C1(-7.5,5.5) C2(-6.5,5.5) C3(-5.5,5.5) C4(-4.5,5.5) C5(-3.5,5.5) C6(-2.5,5.5) C7(-1.5,5.5) C8(-0.5,5.5) C9(0.5,5.5) C10(1.5,5.5) C11(2.5,5.5) C12(3.5,5.5) C13(4.5,5.5) C14(5.5,5.5) C15(6.5,5.5) C16(7.5,5.5) D1(-7.5,4.5) D2(-6.5,4.5) D3(-5.5,4.5) D4(-4.5,4.5) D5(-3.5,4.5) D6(-2.5,4.5) D7(-1.5,4.5) D8(-0.5,4.5) D9(0.5,4.5) D10(1.5,4.5) D11(2.5,4.5) D12(3.5,4.5) D13(4.5,4.5) D14(5.5,4.5) D15(6.5,4.5) D16(7.5,4.5) E1(-7.5,3.5) E2(-6.5,3.5) E3(-5.5,3.5) E4(-4.5,3.5) E5(-3.5,3.5) E6(-2.5,3.5) E7(-1.5,3.5) E8(-0.5,3.5) E9(0.5,3.5) E10(1.5,3.5) E11(2.5,3.5) E12(3.5,3.5) E13(4.5,3.5) E14(5.5,3.5) E15(6.5,3.5) E16(7.5,3.5) F1(-7.5,2.5) F2(-6.5,2.5) F3(-5.5,2.5) F4(-4.5,2.5) F5(-3.5,2.5) F6(-2.5,2.5) F7(-1.5,2.5) F8(-0.5,2.5) F9(0.5,2.5) F10(1.5,2.5) F11(2.5,2.5) F12(3.5,2.5) F13(4.5,2.5) F14(5.5,2.5) F15(6.5,2.5) F16(7.5,2.5) G1(-7.5,1.5) G2(-6.5,1.5) G3(-5.5,1.5) G4(-4.5,1.5) G5(-3.5,1.5) G6(-2.5,1.5) G7(-1.5,1.5) G8(-0.5,1.5) G9(0.5,1.5) G10(1.5,1.5) G11(2.5,1.5) G12(3.5,1.5) G13(4.5,1.5) G14(5.5,1.5) G15(6.5,1.5) G16(7.5,1.5) H1(-7.5,0.5) H2(-6.5,0.5) H3(-5.5,0.5) H4(-4.5,0.5) H5(-3.5,0.5) H6(-2.5,0.5) H7(-1.5,0.5) H8(-0.5,0.5) H9(0.5,0.5) H10(1.5,0.5) H11(2.5,0.5) H12(3.5,0.5) H13(4.5,0.5) H14(5.5,0.5) H15(6.5,0.5) H16(7.5,0.5) J1(-7.5,-0.5) J2(-6.5,-0.5) J3(-5.5,-0.5) J4(-4.5,-0.5) J5(-3.5,-0.5) J6(-2.5,-0.5) J7(-1.5,-0.5) J8(-0.5,-0.5) J9(0.5,-0.5) J10(1.5,-0.5) J11(2.5,-0.5) J12(3.5,-0.5) J13(4.5,-0.5) J14(5.5,-0.5) J15(6.5,-0.5) J16(7.5,-0.5) K1(-7.5,-1.5) K2(-6.5,-1.5) K3(-5.5,-1.5) K4(-4.5,-1.5) K5(-3.5,-1.5) K6(-2.5,-1.5) K7(-1.5,-1.5) K8(-0.5,-1.5) K9(0.5,-1.5) K10(1.5,-1.5) K11(2.5,-1.5) K12(3.5,-1.5) K13(4.5,-1.5) K14(5.5,-1.5) K15(6.5,-1.5) K16(7.5,-1.5) L1(-7.5,-2.5) L2(-6.5,-2.5) L3(-5.5,-2.5) L4(-4.5,-2.5) L5(-3.5,-2.5) L6(-2.5,-2.5) L7(-1.5,-2.5) L8(-0.5,-2.5) L9(0.5,-2.5) L10(1.5,-2.5) L11(2.5,-2.5) L12(3.5,-2.5) L13(4.5,-2.5) L14(5.5,-2.5) L15(6.5,-2.5) L16(7.5,-2.5) M1(-7.5,-3.5) M2(-6.5,-3.5) M3(-5.5,-3.5) M4(-4.5,-3.5) M5(-3.5,-3.5) M6(-2.5,-3.5) M7(-1.5,-3.5) M8(-0.5,-3.5) M9(0.5,-3.5) M10(1.5,-3.5) M11(2.5,-3.5) M12(3.5,-3.5) M13(4.5,-3.5) M14(5.5,-3.5) M15(6.5,-3.5) M16(7.5,-3.5) N1(-7.5,-4.5) N2(-6.5,-4.5) N3(-5.5,-4.5) N4(-4.5,-4.5) N5(-3.5,-4.5) N6(-2.5,-4.5) N7(-1.5,-4.5) N8(-0.5,-4.5) N9(0.5,-4.5) N10(1.5,-4.5) N11(2.5,-4.5) N12(3.5,-4.5) N13(4.5,-4.5) N14(5.5,-4.5) N15(6.5,-4.5) N16(7.5,-4.5) P1(-7.5,-5.5) P2(-6.5,-5.5) P3(-5.5,-5.5) P4(-4.5,-5.5) P5(-3.5,-5.5) P6(-2.5,-5.5) P7(-1.5,-5.5) P8(-0.5,-5.5) P9(0.5,-5.5) P10(1.5,-5.5) P11(2.5,-5.5) P12(3.5,-5.5) P13(4.5,-5.5) P14(5.5,-5.5) P15(6.5,-5.5) P16(7.5,-5.5) R1(-7.5,-6.5) R2(-6.5,-6.5) R3(-5.5,-6.5) R4(-4.5,-6.5) R5(-3.5,-6.5) R6(-2.5,-6.5) R7(-1.5,-6.5) R8(-0.5,-6.5) R9(0.5,-6.5) R10(1.5,-6.5) R11(2.5,-6.5) R12(3.5,-6.5) R13(4.5,-6.5) R14(5.5,-6.5) R15(6.5,-6.5) R16(7.5,-6.5) T1(-7.5,-7.5) T2(-6.5,-7.5) T3(-5.5,-7.5) T4(-4.5,-7.5) T5(-3.5,-7.5) T6(-2.5,-7.5) T7(-1.5,-7.5) T8(-0.5,-7.5) T9(0.5,-7.5) T10(1.5,-7.5) T11(2.5,-7.5) T12(3.5,-7.5) T13(4.5,-7.5) T14(5.5,-7.5) T15(6.5,-7.5) T16(7.5,-7.5)
Top Overlay:
  circle w0.25: c-9.15,7.5 r0.125
  lines w0.2: -8.5,-7.5 -8.5,8.5 7.5,8.5 8.5,7.5 8.5,-7.5 7.5,-8.5 -7.5,-8.5 -8.5,-7.5 ; 7.581,-8.5 7.581,-8.5 ; 8.5,7.581 8.5,7.581

## BGA17X17-B256/X.4 [mm]
pads (256):
  round 0.4 smd: A1(-7.5,7.5) A2(-6.5,7.5) A3(-5.5,7.5) A4(-4.5,7.5) A5(-3.5,7.5) A6(-2.5,7.5) A7(-1.5,7.5) A8(-0.5,7.5) A9(0.5,7.5) A10(1.5,7.5) A11(2.5,7.5) A12(3.5,7.5) A13(4.5,7.5) A14(5.5,7.5) A15(6.5,7.5) A16(7.5,7.5) B1(-7.5,6.5) B2(-6.5,6.5) B3(-5.5,6.5) B4(-4.5,6.5) B5(-3.5,6.5) B6(-2.5,6.5) B7(-1.5,6.5) B8(-0.5,6.5) B9(0.5,6.5) B10(1.5,6.5) B11(2.5,6.5) B12(3.5,6.5) B13(4.5,6.5) B14(5.5,6.5) B15(6.5,6.5) B16(7.5,6.5) C1(-7.5,5.5) C2(-6.5,5.5) C3(-5.5,5.5) C4(-4.5,5.5) C5(-3.5,5.5) C6(-2.5,5.5) C7(-1.5,5.5) C8(-0.5,5.5) C9(0.5,5.5) C10(1.5,5.5) C11(2.5,5.5) C12(3.5,5.5) C13(4.5,5.5) C14(5.5,5.5) C15(6.5,5.5) C16(7.5,5.5) D1(-7.5,4.5) D2(-6.5,4.5) D3(-5.5,4.5) D4(-4.5,4.5) D5(-3.5,4.5) D6(-2.5,4.5) D7(-1.5,4.5) D8(-0.5,4.5) D9(0.5,4.5) D10(1.5,4.5) D11(2.5,4.5) D12(3.5,4.5) D13(4.5,4.5) D14(5.5,4.5) D15(6.5,4.5) D16(7.5,4.5) E1(-7.5,3.5) E2(-6.5,3.5) E3(-5.5,3.5) E4(-4.5,3.5) E5(-3.5,3.5) E6(-2.5,3.5) E7(-1.5,3.5) E8(-0.5,3.5) E9(0.5,3.5) E10(1.5,3.5) E11(2.5,3.5) E12(3.5,3.5) E13(4.5,3.5) E14(5.5,3.5) E15(6.5,3.5) E16(7.5,3.5) F1(-7.5,2.5) F2(-6.5,2.5) F3(-5.5,2.5) F4(-4.5,2.5) F5(-3.5,2.5) F6(-2.5,2.5) F7(-1.5,2.5) F8(-0.5,2.5) F9(0.5,2.5) F10(1.5,2.5) F11(2.5,2.5) F12(3.5,2.5) F13(4.5,2.5) F14(5.5,2.5) F15(6.5,2.5) F16(7.5,2.5) G1(-7.5,1.5) G2(-6.5,1.5) G3(-5.5,1.5) G4(-4.5,1.5) G5(-3.5,1.5) G6(-2.5,1.5) G7(-1.5,1.5) G8(-0.5,1.5) G9(0.5,1.5) G10(1.5,1.5) G11(2.5,1.5) G12(3.5,1.5) G13(4.5,1.5) G14(5.5,1.5) G15(6.5,1.5) G16(7.5,1.5) H1(-7.5,0.5) H2(-6.5,0.5) H3(-5.5,0.5) H4(-4.5,0.5) H5(-3.5,0.5) H6(-2.5,0.5) H7(-1.5,0.5) H8(-0.5,0.5) H9(0.5,0.5) H10(1.5,0.5) H11(2.5,0.5) H12(3.5,0.5) H13(4.5,0.5) H14(5.5,0.5) H15(6.5,0.5) H16(7.5,0.5) J1(-7.5,-0.5) J2(-6.5,-0.5) J3(-5.5,-0.5) J4(-4.5,-0.5) J5(-3.5,-0.5) J6(-2.5,-0.5) J7(-1.5,-0.5) J8(-0.5,-0.5) J9(0.5,-0.5) J10(1.5,-0.5) J11(2.5,-0.5) J12(3.5,-0.5) J13(4.5,-0.5) J14(5.5,-0.5) J15(6.5,-0.5) J16(7.5,-0.5) K1(-7.5,-1.5) K2(-6.5,-1.5) K3(-5.5,-1.5) K4(-4.5,-1.5) K5(-3.5,-1.5) K6(-2.5,-1.5) K7(-1.5,-1.5) K8(-0.5,-1.5) K9(0.5,-1.5) K10(1.5,-1.5) K11(2.5,-1.5) K12(3.5,-1.5) K13(4.5,-1.5) K14(5.5,-1.5) K15(6.5,-1.5) K16(7.5,-1.5) L1(-7.5,-2.5) L2(-6.5,-2.5) L3(-5.5,-2.5) L4(-4.5,-2.5) L5(-3.5,-2.5) L6(-2.5,-2.5) L7(-1.5,-2.5) L8(-0.5,-2.5) L9(0.5,-2.5) L10(1.5,-2.5) L11(2.5,-2.5) L12(3.5,-2.5) L13(4.5,-2.5) L14(5.5,-2.5) L15(6.5,-2.5) L16(7.5,-2.5) M1(-7.5,-3.5) M2(-6.5,-3.5) M3(-5.5,-3.5) M4(-4.5,-3.5) M5(-3.5,-3.5) M6(-2.5,-3.5) M7(-1.5,-3.5) M8(-0.5,-3.5) M9(0.5,-3.5) M10(1.5,-3.5) M11(2.5,-3.5) M12(3.5,-3.5) M13(4.5,-3.5) M14(5.5,-3.5) M15(6.5,-3.5) M16(7.5,-3.5) N1(-7.5,-4.5) N2(-6.5,-4.5) N3(-5.5,-4.5) N4(-4.5,-4.5) N5(-3.5,-4.5) N6(-2.5,-4.5) N7(-1.5,-4.5) N8(-0.5,-4.5) N9(0.5,-4.5) N10(1.5,-4.5) N11(2.5,-4.5) N12(3.5,-4.5) N13(4.5,-4.5) N14(5.5,-4.5) N15(6.5,-4.5) N16(7.5,-4.5) P1(-7.5,-5.5) P2(-6.5,-5.5) P3(-5.5,-5.5) P4(-4.5,-5.5) P5(-3.5,-5.5) P6(-2.5,-5.5) P7(-1.5,-5.5) P8(-0.5,-5.5) P9(0.5,-5.5) P10(1.5,-5.5) P11(2.5,-5.5) P12(3.5,-5.5) P13(4.5,-5.5) P14(5.5,-5.5) P15(6.5,-5.5) P16(7.5,-5.5) R1(-7.5,-6.5) R2(-6.5,-6.5) R3(-5.5,-6.5) R4(-4.5,-6.5) R5(-3.5,-6.5) R6(-2.5,-6.5) R7(-1.5,-6.5) R8(-0.5,-6.5) R9(0.5,-6.5) R10(1.5,-6.5) R11(2.5,-6.5) R12(3.5,-6.5) R13(4.5,-6.5) R14(5.5,-6.5) R15(6.5,-6.5) R16(7.5,-6.5) T1(-7.5,-7.5) T2(-6.5,-7.5) T3(-5.5,-7.5) T4(-4.5,-7.5) T5(-3.5,-7.5) T6(-2.5,-7.5) T7(-1.5,-7.5) T8(-0.5,-7.5) T9(0.5,-7.5) T10(1.5,-7.5) T11(2.5,-7.5) T12(3.5,-7.5) T13(4.5,-7.5) T14(5.5,-7.5) T15(6.5,-7.5) T16(7.5,-7.5)
Top Overlay:
  circle w0.25: c-9.15,7.5 r0.125
  lines w0.2: -8.5,-7.5 -7.5,-8.5 7.5,-8.5 8.5,-7.5 8.5,7.5 7.5,8.5 -8.5,8.5 -8.5,-7.5

## BGA17X17-B256/X.45 [mm]
pads (256):
  round 0.45 smd: A1(-7.5,7.5) A2(-6.5,7.5) A3(-5.5,7.5) A4(-4.5,7.5) A5(-3.5,7.5) A6(-2.5,7.5) A7(-1.5,7.5) A8(-0.5,7.5) A9(0.5,7.5) A10(1.5,7.5) A11(2.5,7.5) A12(3.5,7.5) A13(4.5,7.5) A14(5.5,7.5) A15(6.5,7.5) A16(7.5,7.5) B1(-7.5,6.5) B2(-6.5,6.5) B3(-5.5,6.5) B4(-4.5,6.5) B5(-3.5,6.5) B6(-2.5,6.5) B7(-1.5,6.5) B8(-0.5,6.5) B9(0.5,6.5) B10(1.5,6.5) B11(2.5,6.5) B12(3.5,6.5) B13(4.5,6.5) B14(5.5,6.5) B15(6.5,6.5) B16(7.5,6.5) C1(-7.5,5.5) C2(-6.5,5.5) C3(-5.5,5.5) C4(-4.5,5.5) C5(-3.5,5.5) C6(-2.5,5.5) C7(-1.5,5.5) C8(-0.5,5.5) C9(0.5,5.5) C10(1.5,5.5) C11(2.5,5.5) C12(3.5,5.5) C13(4.5,5.5) C14(5.5,5.5) C15(6.5,5.5) C16(7.5,5.5) D1(-7.5,4.5) D2(-6.5,4.5) D3(-5.5,4.5) D4(-4.5,4.5) D5(-3.5,4.5) D6(-2.5,4.5) D7(-1.5,4.5) D8(-0.5,4.5) D9(0.5,4.5) D10(1.5,4.5) D11(2.5,4.5) D12(3.5,4.5) D13(4.5,4.5) D14(5.5,4.5) D15(6.5,4.5) D16(7.5,4.5) E1(-7.5,3.5) E2(-6.5,3.5) E3(-5.5,3.5) E4(-4.5,3.5) E5(-3.5,3.5) E6(-2.5,3.5) E7(-1.5,3.5) E8(-0.5,3.5) E9(0.5,3.5) E10(1.5,3.5) E11(2.5,3.5) E12(3.5,3.5) E13(4.5,3.5) E14(5.5,3.5) E15(6.5,3.5) E16(7.5,3.5) F1(-7.5,2.5) F2(-6.5,2.5) F3(-5.5,2.5) F4(-4.5,2.5) F5(-3.5,2.5) F6(-2.5,2.5) F7(-1.5,2.5) F8(-0.5,2.5) F9(0.5,2.5) F10(1.5,2.5) F11(2.5,2.5) F12(3.5,2.5) F13(4.5,2.5) F14(5.5,2.5) F15(6.5,2.5) F16(7.5,2.5) G1(-7.5,1.5) G2(-6.5,1.5) G3(-5.5,1.5) G4(-4.5,1.5) G5(-3.5,1.5) G6(-2.5,1.5) G7(-1.5,1.5) G8(-0.5,1.5) G9(0.5,1.5) G10(1.5,1.5) G11(2.5,1.5) G12(3.5,1.5) G13(4.5,1.5) G14(5.5,1.5) G15(6.5,1.5) G16(7.5,1.5) H1(-7.5,0.5) H2(-6.5,0.5) H3(-5.5,0.5) H4(-4.5,0.5) H5(-3.5,0.5) H6(-2.5,0.5) H7(-1.5,0.5) H8(-0.5,0.5) H9(0.5,0.5) H10(1.5,0.5) H11(2.5,0.5) H12(3.5,0.5) H13(4.5,0.5) H14(5.5,0.5) H15(6.5,0.5) H16(7.5,0.5) J1(-7.5,-0.5) J2(-6.5,-0.5) J3(-5.5,-0.5) J4(-4.5,-0.5) J5(-3.5,-0.5) J6(-2.5,-0.5) J7(-1.5,-0.5) J8(-0.5,-0.5) J9(0.5,-0.5) J10(1.5,-0.5) J11(2.5,-0.5) J12(3.5,-0.5) J13(4.5,-0.5) J14(5.5,-0.5) J15(6.5,-0.5) J16(7.5,-0.5) K1(-7.5,-1.5) K2(-6.5,-1.5) K3(-5.5,-1.5) K4(-4.5,-1.5) K5(-3.5,-1.5) K6(-2.5,-1.5) K7(-1.5,-1.5) K8(-0.5,-1.5) K9(0.5,-1.5) K10(1.5,-1.5) K11(2.5,-1.5) K12(3.5,-1.5) K13(4.5,-1.5) K14(5.5,-1.5) K15(6.5,-1.5) K16(7.5,-1.5) L1(-7.5,-2.5) L2(-6.5,-2.5) L3(-5.5,-2.5) L4(-4.5,-2.5) L5(-3.5,-2.5) L6(-2.5,-2.5) L7(-1.5,-2.5) L8(-0.5,-2.5) L9(0.5,-2.5) L10(1.5,-2.5) L11(2.5,-2.5) L12(3.5,-2.5) L13(4.5,-2.5) L14(5.5,-2.5) L15(6.5,-2.5) L16(7.5,-2.5) M1(-7.5,-3.5) M2(-6.5,-3.5) M3(-5.5,-3.5) M4(-4.5,-3.5) M5(-3.5,-3.5) M6(-2.5,-3.5) M7(-1.5,-3.5) M8(-0.5,-3.5) M9(0.5,-3.5) M10(1.5,-3.5) M11(2.5,-3.5) M12(3.5,-3.5) M13(4.5,-3.5) M14(5.5,-3.5) M15(6.5,-3.5) M16(7.5,-3.5) N1(-7.5,-4.5) N2(-6.5,-4.5) N3(-5.5,-4.5) N4(-4.5,-4.5) N5(-3.5,-4.5) N6(-2.5,-4.5) N7(-1.5,-4.5) N8(-0.5,-4.5) N9(0.5,-4.5) N10(1.5,-4.5) N11(2.5,-4.5) N12(3.5,-4.5) N13(4.5,-4.5) N14(5.5,-4.5) N15(6.5,-4.5) N16(7.5,-4.5) P1(-7.5,-5.5) P2(-6.5,-5.5) P3(-5.5,-5.5) P4(-4.5,-5.5) P5(-3.5,-5.5) P6(-2.5,-5.5) P7(-1.5,-5.5) P8(-0.5,-5.5) P9(0.5,-5.5) P10(1.5,-5.5) P11(2.5,-5.5) P12(3.5,-5.5) P13(4.5,-5.5) P14(5.5,-5.5) P15(6.5,-5.5) P16(7.5,-5.5) R1(-7.5,-6.5) R2(-6.5,-6.5) R3(-5.5,-6.5) R4(-4.5,-6.5) R5(-3.5,-6.5) R6(-2.5,-6.5) R7(-1.5,-6.5) R8(-0.5,-6.5) R9(0.5,-6.5) R10(1.5,-6.5) R11(2.5,-6.5) R12(3.5,-6.5) R13(4.5,-6.5) R14(5.5,-6.5) R15(6.5,-6.5) R16(7.5,-6.5) T1(-7.5,-7.5) T2(-6.5,-7.5) T3(-5.5,-7.5) T4(-4.5,-7.5) T5(-3.5,-7.5) T6(-2.5,-7.5) T7(-1.5,-7.5) T8(-0.5,-7.5) T9(0.5,-7.5) T10(1.5,-7.5) T11(2.5,-7.5) T12(3.5,-7.5) T13(4.5,-7.5) T14(5.5,-7.5) T15(6.5,-7.5) T16(7.5,-7.5)
Top Overlay:
  circle w0.25: c-9.15,7.5 r0.125
  lines w0.2: -8.5,-7.384 -7.384,-8.5 7.384,-8.5 8.5,-7.384 8.5,7.384 7.384,8.5 -8.5,8.5 -8.5,-7.384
